// Mitsubishi GX Works2 project: 30.8按钮点动（4常开4常闭）   PLC: FX3U/FX3UC

PROGRAM MAIN
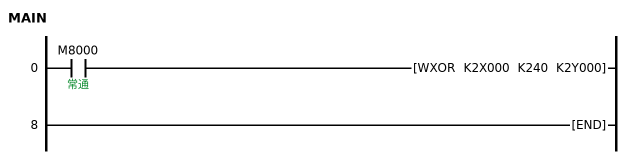
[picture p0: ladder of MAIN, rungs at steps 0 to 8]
0     LD      M8000  ; 常通
      WXOR    K2X000 K240 K2Y000
8     END
END_PROGRAM
